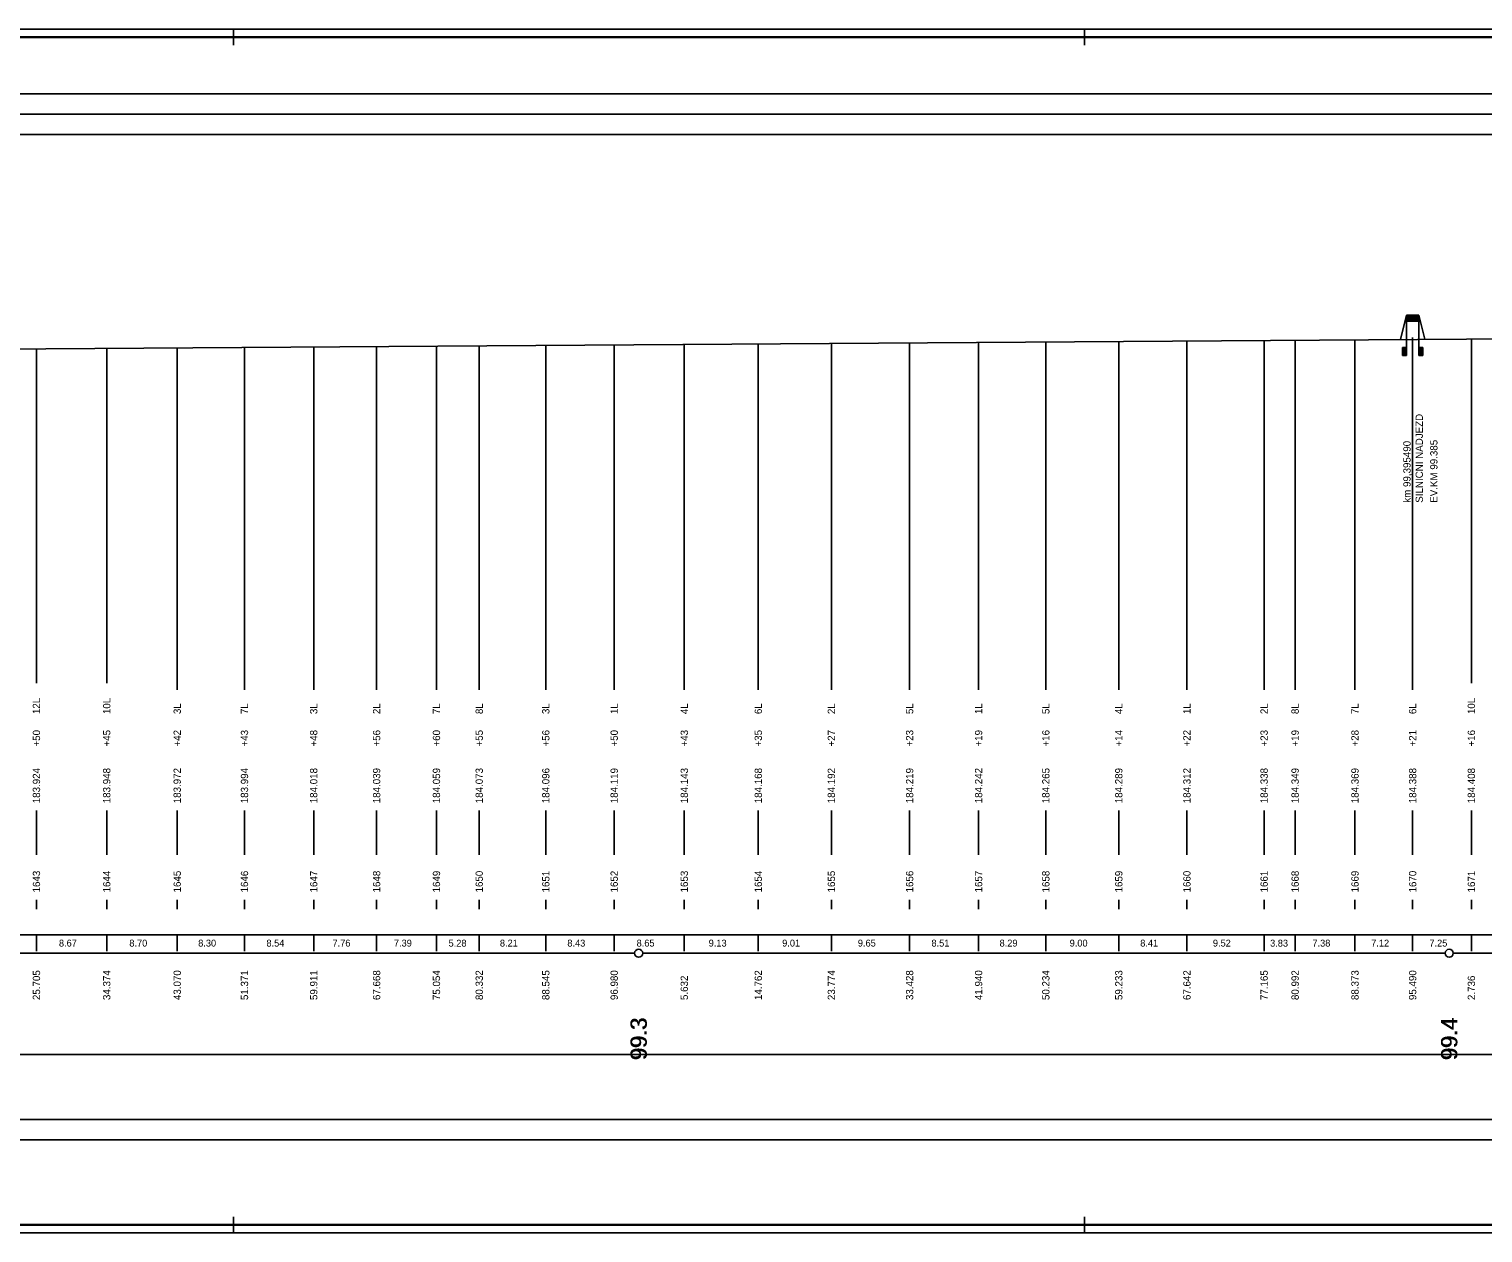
# Model space of a CAD drawing. Extents: x 0 to 10087, y -805 to 297.
# Drawn here: x 5829.6 to 6188.3, y 0 to 297 of the extents above; entities that cross this region are included whole.
import ezdxf

# ---------------------------------------------------------------- set-up
doc = ezdxf.new("R2010")
doc.units = 0
for name, color, linetype in [('CARKY_HODNOT', 7, 'Continuous'), ('KRIV1_CARA', 7, 'Continuous'), ('NIVELETA_CARA', 7, 'Continuous'), ('OBJEKTY_TEXT', 7, 'Continuous'), ('OBJEKTY_TVAR', 7, 'Continuous'), ('RAM', 7, 'Continuous'), ('REZERVA', 7, 'Continuous'), ('STAN_CARA', 7, 'Continuous'), ('STAN_PAS', 7, 'Continuous'), ('STAN_TEXT', 7, 'Continuous'), ('TEXT', 7, 'Continuous'), ('TXT_C_BODU', 7, 'Continuous')]:
    doc.layers.add(name, color=color, linetype=linetype)

msp = doc.modelspace()

# ---------------------------------------------------------------- linework, layer by layer
at = {"layer": 'CARKY_HODNOT'}
for p, q in [((5940.66, 138.35), (5940.66, 218.87)), ((5957.09, 138.35), (5957.09, 218.98)), ((5973.96, 138.35), (5973.96, 219.09)), ((5991.26, 138.35), (5991.26, 219.21)), ((6009.52, 138.35), (6009.52, 219.34)), ((6027.55, 138.35), (6027.55, 219.46)), ((6046.86, 138.35), (6046.86, 219.59)), ((6063.88, 138.35), (6063.88, 219.71)), ((6080.47, 138.35), (6080.47, 219.82)), ((6098.47, 138.35), (6098.47, 219.95)), ((6115.28, 138.35), (6115.28, 220.06)), ((6134.33, 138.35), (6134.33, 220.19)), ((6141.98, 138.35), (6141.98, 220.24)), ((6156.75, 138.35), (6156.75, 220.34)), ((6170.98, 138.35), (6170.98, 220.44)), ((6185.47, 138.35), (6185.47, 220.54)), ((5831.41, 138.35), (5831.41, 218.12)), ((5848.75, 138.35), (5848.75, 218.24)), ((5866.14, 138.35), (5866.14, 218.36)), ((5882.74, 138.35), (5882.74, 218.47)), ((5899.82, 138.35), (5899.82, 218.59)), ((5915.34, 138.35), (5915.34, 218.69)), ((5930.11, 138.35), (5930.11, 218.8)), ((5831.41, 135.65), (5831.41, 138.35)), ((5848.75, 135.65), (5848.75, 138.35)), ((5866.14, 134), (5866.14, 138.35)), ((5882.74, 134), (5882.74, 138.35)), ((5899.82, 134), (5899.82, 138.35)), ((5915.34, 134), (5915.34, 138.35)), ((5930.11, 134), (5930.11, 138.35)), ((5940.66, 134), (5940.66, 138.35)), ((5957.09, 134), (5957.09, 138.35)), ((5973.96, 134), (5973.96, 138.35)), ((5991.26, 134), (5991.26, 138.35)), ((6009.52, 134), (6009.52, 138.35)), ((6027.55, 134), (6027.55, 138.35)), ((6046.86, 134), (6046.86, 138.35)), ((6063.88, 134), (6063.88, 138.35)), ((6080.47, 134), (6080.47, 138.35)), ((6098.47, 134), (6098.47, 138.35)), ((6115.28, 134), (6115.28, 138.35)), ((6134.33, 134), (6134.33, 138.35)), ((6141.98, 134), (6141.98, 138.35)), ((6156.75, 134), (6156.75, 138.35)), ((6170.98, 134), (6170.98, 138.35)), ((6185.47, 135.65), (6185.47, 138.35)), ((5831.41, 93.3), (5831.41, 104.2)), ((5848.75, 93.3), (5848.75, 104.2)), ((5866.14, 93.3), (5866.14, 104.2)), ((5882.74, 93.3), (5882.74, 104.2)), ((5899.82, 93.3), (5899.82, 104.2)), ((5915.34, 93.3), (5915.34, 104.2)), ((5930.11, 93.3), (5930.11, 104.2)), ((5940.66, 93.3), (5940.66, 104.2)), ((5957.09, 93.3), (5957.09, 104.2)), ((5973.96, 93.3), (5973.96, 104.2)), ((5991.26, 93.3), (5991.26, 104.2)), ((6009.52, 93.3), (6009.52, 104.2)), ((6027.55, 93.3), (6027.55, 104.2)), ((6046.86, 93.3), (6046.86, 104.2)), ((6063.88, 93.3), (6063.88, 104.2)), ((6080.47, 93.3), (6080.47, 104.2)), ((6098.47, 93.3), (6098.47, 104.2)), ((6115.28, 93.3), (6115.28, 104.2)), ((6134.33, 93.3), (6134.33, 104.2)), ((6141.98, 93.3), (6141.98, 104.2)), ((6156.75, 93.3), (6156.75, 104.2)), ((6170.98, 93.3), (6170.98, 104.2)), ((6185.47, 93.3), (6185.47, 104.2)), ((5831.41, 79.9), (5831.41, 82.2)), ((5848.75, 79.9), (5848.75, 82.2)), ((5866.14, 79.9), (5866.14, 82.2)), ((5882.74, 79.9), (5882.74, 82.2)), ((5899.82, 79.9), (5899.82, 82.2)), ((5915.34, 79.9), (5915.34, 82.2)), ((5930.11, 79.9), (5930.11, 82.2)), ((5940.66, 79.9), (5940.66, 82.2)), ((5957.09, 79.9), (5957.09, 82.2)), ((5973.96, 79.9), (5973.96, 82.2)), ((5991.26, 79.9), (5991.26, 82.2)), ((6009.52, 79.9), (6009.52, 82.2)), ((6027.55, 79.9), (6027.55, 82.2)), ((6046.86, 79.9), (6046.86, 82.2)), ((6063.88, 79.9), (6063.88, 82.2)), ((6080.47, 79.9), (6080.47, 82.2)), ((6098.47, 79.9), (6098.47, 82.2)), ((6115.28, 79.9), (6115.28, 82.2)), ((6134.33, 79.9), (6134.33, 82.2)), ((6141.98, 79.9), (6141.98, 82.2)), ((6156.75, 79.9), (6156.75, 82.2)), ((6170.98, 79.9), (6170.98, 82.2)), ((6185.47, 79.9), (6185.47, 82.2))]:
    msp.add_line(p, q, dxfattribs=at)
at = {"layer": 'KRIV1_CARA'}
msp.add_line((5093.47, 44), (6545.11, 44), dxfattribs=at)
at = {"layer": 'NIVELETA_CARA'}
for p, q in [((300, 281), (8321.33, 281)), ((300, 276), (8321.33, 276)), ((300, 271), (8321.33, 271)), ((5576.72, 216.38), (6267.07, 221.1)), ((500, 28), (8321.33, 28)), ((500, 23), (8321.33, 23))]:
    msp.add_line(p, q, dxfattribs=at)
at = {"layer": 'OBJEKTY_TVAR'}
for p, q in [((6167.98, 220.42), (6169.48, 226.44)), ((6169.48, 216.44), (6169.48, 226.44)), ((6169.48, 226.44), (6172.48, 226.44)), ((6169.48, 226.24), (6172.48, 226.24)), ((6169.48, 226.04), (6172.48, 226.04)), ((6172.48, 226.44), (6172.48, 216.44)), ((6173.98, 220.46), (6172.48, 226.44)), ((6169.48, 225.84), (6172.48, 225.84)), ((6169.48, 225.64), (6172.48, 225.64)), ((6169.48, 225.44), (6172.48, 225.44)), ((6169.48, 225.24), (6172.48, 225.24)), ((6169.48, 225.04), (6172.48, 225.04)), ((6169.48, 224.94), (6172.48, 224.94)), ((6170.98, 219.94), (6170.98, 220.94)), ((6169.48, 218.44), (6168.48, 218.44)), ((6168.48, 218.44), (6168.48, 216.44)), ((6168.48, 216.44), (6169.48, 216.44)), ((6168.73, 218.44), (6168.73, 216.44)), ((6168.98, 218.44), (6168.98, 216.44)), ((6169.23, 218.44), (6169.23, 216.44)), ((6173.48, 218.44), (6172.48, 218.44)), ((6172.48, 216.44), (6173.48, 216.44)), ((6172.73, 218.44), (6172.73, 216.44)), ((6172.98, 218.44), (6172.98, 216.44)), ((6173.23, 218.44), (6173.23, 216.44)), ((6173.48, 216.44), (6173.48, 218.44))]:
    msp.add_line(p, q, dxfattribs=at)
at = {"layer": 'RAM'}
for p, q in [((8636.33, 297), (0, 297)), ((8634.33, 295.1), (2, 295.1)), ((8634.33, 295), (2, 295)), ((8634.33, 294.9), (2, 294.9)), ((5880, 293), (5880, 297)), ((6090, 293), (6090, 297)), ((5880, 0), (5880, 4)), ((6090, 0), (6090, 4)), ((0, 0), (8636.33, 0)), ((2, 2.1), (8634.33, 2.1)), ((2, 2), (8634.33, 2)), ((2, 1.9), (8634.33, 1.9))]:
    msp.add_line(p, q, dxfattribs=at)
at = {"layer": 'REZERVA'}
for centre in [(5980, 69), (6180, 69)]:
    msp.add_circle(centre, 1, dxfattribs=at)
at = {"layer": 'STAN_CARA'}
for p, q in [((5781, 69), (5979, 69)), ((5981, 69), (6179, 69)), ((6181, 69), (6379, 69))]:
    msp.add_line(p, q, dxfattribs=at)
at = {"layer": 'STAN_PAS'}
for p, q in [((300, 73.5), (8321.33, 73.5)), ((5831.41, 69.5), (5831.41, 73.5)), ((5848.75, 69.5), (5848.75, 73.5)), ((5866.14, 69.5), (5866.14, 73.5)), ((5882.74, 69.5), (5882.74, 73.5)), ((5899.82, 69.5), (5899.82, 73.5)), ((5915.34, 69.5), (5915.34, 73.5)), ((5930.11, 69.5), (5930.11, 73.5)), ((5940.66, 69.5), (5940.66, 73.5)), ((5957.09, 69.5), (5957.09, 73.5)), ((5973.96, 69.5), (5973.96, 73.5)), ((5991.26, 69.5), (5991.26, 73.5)), ((6009.52, 69.5), (6009.52, 73.5)), ((6027.55, 69.5), (6027.55, 73.5)), ((6046.86, 69.5), (6046.86, 73.5)), ((6063.88, 69.5), (6063.88, 73.5)), ((6080.47, 69.5), (6080.47, 73.5)), ((6098.47, 69.5), (6098.47, 73.5)), ((6115.28, 69.5), (6115.28, 73.5)), ((6134.33, 69.5), (6134.33, 73.5)), ((6141.98, 69.5), (6141.98, 73.5)), ((6156.75, 69.5), (6156.75, 73.5)), ((6170.98, 69.5), (6170.98, 73.5)), ((6185.47, 69.5), (6185.47, 73.5))]:
    msp.add_line(p, q, dxfattribs=at)

# ---------------------------------------------------------------- texts
at = {"layer": 'OBJEKTY_TEXT'}
for s, p in [('SILNICNI NADJEZD', (6173.51, 180.14)), ('km 99,395490', (6170.48, 180.15)), ('EV.KM 99.385', (6177.11, 180.14))]:
    msp.add_text(s, height=1.8, rotation=90, dxfattribs=at).set_placement(p)
at = {"layer": 'STAN_TEXT'}
for s, p in [('8.67', (5836.96, 70.65)), ('8.70', (5854.33, 70.65)), ('8.30', (5871.32, 70.65)), ('8.54', (5888.16, 70.65)), ('7.76', (5904.46, 70.65)), ('7.39', (5919.61, 70.65)), ('5.28', (5933.1, 70.63)), ('8.21', (5945.76, 70.65)), ('8.43', (5962.41, 70.65)), ('8.65', (5979.5, 70.65)), ('9.13', (5997.28, 70.65)), ('9.01', (6015.42, 70.65)), ('9.65', (6034.09, 70.65)), ('8.51', (6052.25, 70.65)), ('8.29', (6069.06, 70.65)), ('9.00', (6086.35, 70.65)), ('8.41', (6103.76, 70.65)), ('9.52', (6121.69, 70.65)), ('3.83', (6135.81, 70.64)), ('7.38', (6146.25, 70.65)), ('7.12', (6160.75, 70.65)), ('7.25', (6175.11, 70.65))]:
    msp.add_text(s, height=1.7, dxfattribs=at).set_placement(p)
for s, height, p in [('25.705', 1.8, (5832.31, 57.45)), ('34.374', 1.8, (5849.65, 57.45)), ('43.070', 1.8, (5867.04, 57.45)), ('51.371', 1.8, (5883.64, 57.45)), ('59.911', 1.8, (5900.72, 57.45)), ('67.668', 1.8, (5916.24, 57.45)), ('75.054', 1.8, (5931.01, 57.45)), ('80.332', 1.8, (5941.56, 57.45)), ('88.545', 1.8, (5957.99, 57.45)), ('96.980', 1.8, (5974.86, 57.45)), ('14.762', 1.8, (6010.42, 57.45)), ('23.774', 1.8, (6028.45, 57.45)), ('33.428', 1.8, (6047.76, 57.45)), ('41.940', 1.8, (6064.78, 57.45)), ('50.234', 1.8, (6081.37, 57.45)), ('59.233', 1.8, (6099.37, 57.45)), ('67.642', 1.8, (6116.18, 57.45)), ('77.165', 1.8, (6135.23, 57.45)), ('80.992', 1.8, (6142.88, 57.45)), ('88.373', 1.8, (6157.65, 57.45)), ('95.490', 1.8, (6171.88, 57.45)), ('5.632', 1.8, (5992.16, 57.45)), ('2.736', 1.8, (6186.37, 57.45)), ('    99.3', 4, (5982, 36.84)), ('    99.3', 4, (5982, 36.74)), ('    99.3', 4, (5982, 36.64)), ('    99.4', 4, (6182, 36.84)), ('    99.4', 4, (6182, 36.74)), ('    99.4', 4, (6182, 36.64))]:
    msp.add_text(s, height=height, rotation=90, dxfattribs=at).set_placement(p)
at = {"layer": 'TEXT'}
for s, p in [('12L', (5832.31, 128)), ('10L', (5849.65, 128)), ('3L', (5867.04, 128)), ('7L', (5883.64, 128)), ('3L', (5900.72, 128)), ('2L', (5916.24, 128)), ('7L', (5931.01, 128)), ('8L', (5941.56, 128)), ('3L', (5957.99, 128)), ('1L', (5974.86, 128)), ('4L', (5992.16, 128)), ('6L', (6010.42, 128)), ('2L', (6028.45, 128)), ('5L', (6047.76, 128)), ('1L', (6064.78, 128)), ('5L', (6081.37, 128)), ('4L', (6099.37, 128)), ('1L', (6116.18, 128)), ('2L', (6135.23, 128)), ('8L', (6142.88, 128)), ('7L', (6157.65, 128)), ('6L', (6171.88, 128)), ('10L', (6186.37, 128)), ('+50', (5832.31, 120)), ('+45', (5849.65, 120)), ('+42', (5867.04, 120)), ('+43', (5883.64, 120)), ('+48', (5900.72, 120)), ('+56', (5916.24, 120)), ('+60', (5931.01, 120)), ('+55', (5941.56, 120)), ('+56', (5957.99, 120)), ('+50', (5974.86, 120)), ('+43', (5992.16, 120)), ('+35', (6010.42, 120)), ('+27', (6028.45, 120)), ('+23', (6047.76, 120)), ('+19', (6064.78, 120)), ('+16', (6081.37, 120)), ('+14', (6099.37, 120)), ('+22', (6116.18, 120)), ('+23', (6135.23, 120)), ('+19', (6142.88, 120)), ('+28', (6157.65, 120)), ('+21', (6171.88, 120)), ('+16', (6186.37, 120)), ('183.924', (5832.31, 106)), ('183.948', (5849.65, 106)), ('183.972', (5867.04, 106)), ('183.994', (5883.64, 106)), ('184.018', (5900.72, 106)), ('184.039', (5916.24, 106)), ('184.059', (5931.01, 106)), ('184.073', (5941.56, 106)), ('184.096', (5957.99, 106)), ('184.119', (5974.86, 106)), ('184.143', (5992.16, 106)), ('184.168', (6010.42, 106)), ('184.192', (6028.45, 106)), ('184.219', (6047.76, 106)), ('184.242', (6064.78, 106)), ('184.265', (6081.37, 106)), ('184.289', (6099.37, 106)), ('184.312', (6116.18, 106)), ('184.338', (6135.23, 106)), ('184.349', (6142.88, 106)), ('184.369', (6157.65, 106)), ('184.388', (6171.88, 106)), ('184.408', (6186.37, 106))]:
    msp.add_text(s, height=1.8, rotation=90, dxfattribs=at).set_placement(p)
at = {"layer": 'TXT_C_BODU'}
for s, p in [('1643', (5832.31, 84)), ('1644', (5849.65, 84)), ('1645', (5867.04, 84)), ('1646', (5883.64, 84)), ('1647', (5900.72, 84)), ('1648', (5916.24, 84)), ('1649', (5931.01, 84)), ('1650', (5941.56, 84)), ('1651', (5957.99, 84)), ('1652', (5974.86, 84)), ('1653', (5992.16, 84)), ('1654', (6010.42, 84)), ('1655', (6028.45, 84)), ('1656', (6047.76, 84)), ('1657', (6064.78, 84)), ('1658', (6081.37, 84)), ('1659', (6099.37, 84)), ('1660', (6116.18, 84)), ('1661', (6135.23, 84)), ('1668', (6142.88, 84)), ('1669', (6157.65, 84)), ('1670', (6171.88, 84)), ('1671', (6186.37, 84))]:
    msp.add_text(s, height=1.8, rotation=90, dxfattribs=at).set_placement(p)

doc.saveas('drawing.dxf')
